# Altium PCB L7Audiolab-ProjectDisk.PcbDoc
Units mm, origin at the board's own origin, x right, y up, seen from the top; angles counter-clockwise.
Board outline 76 x 50 mm, 2 copper layers (Top Layer, Bottom Layer); 50 components, 28 nets, 135 pads, 196 vias.
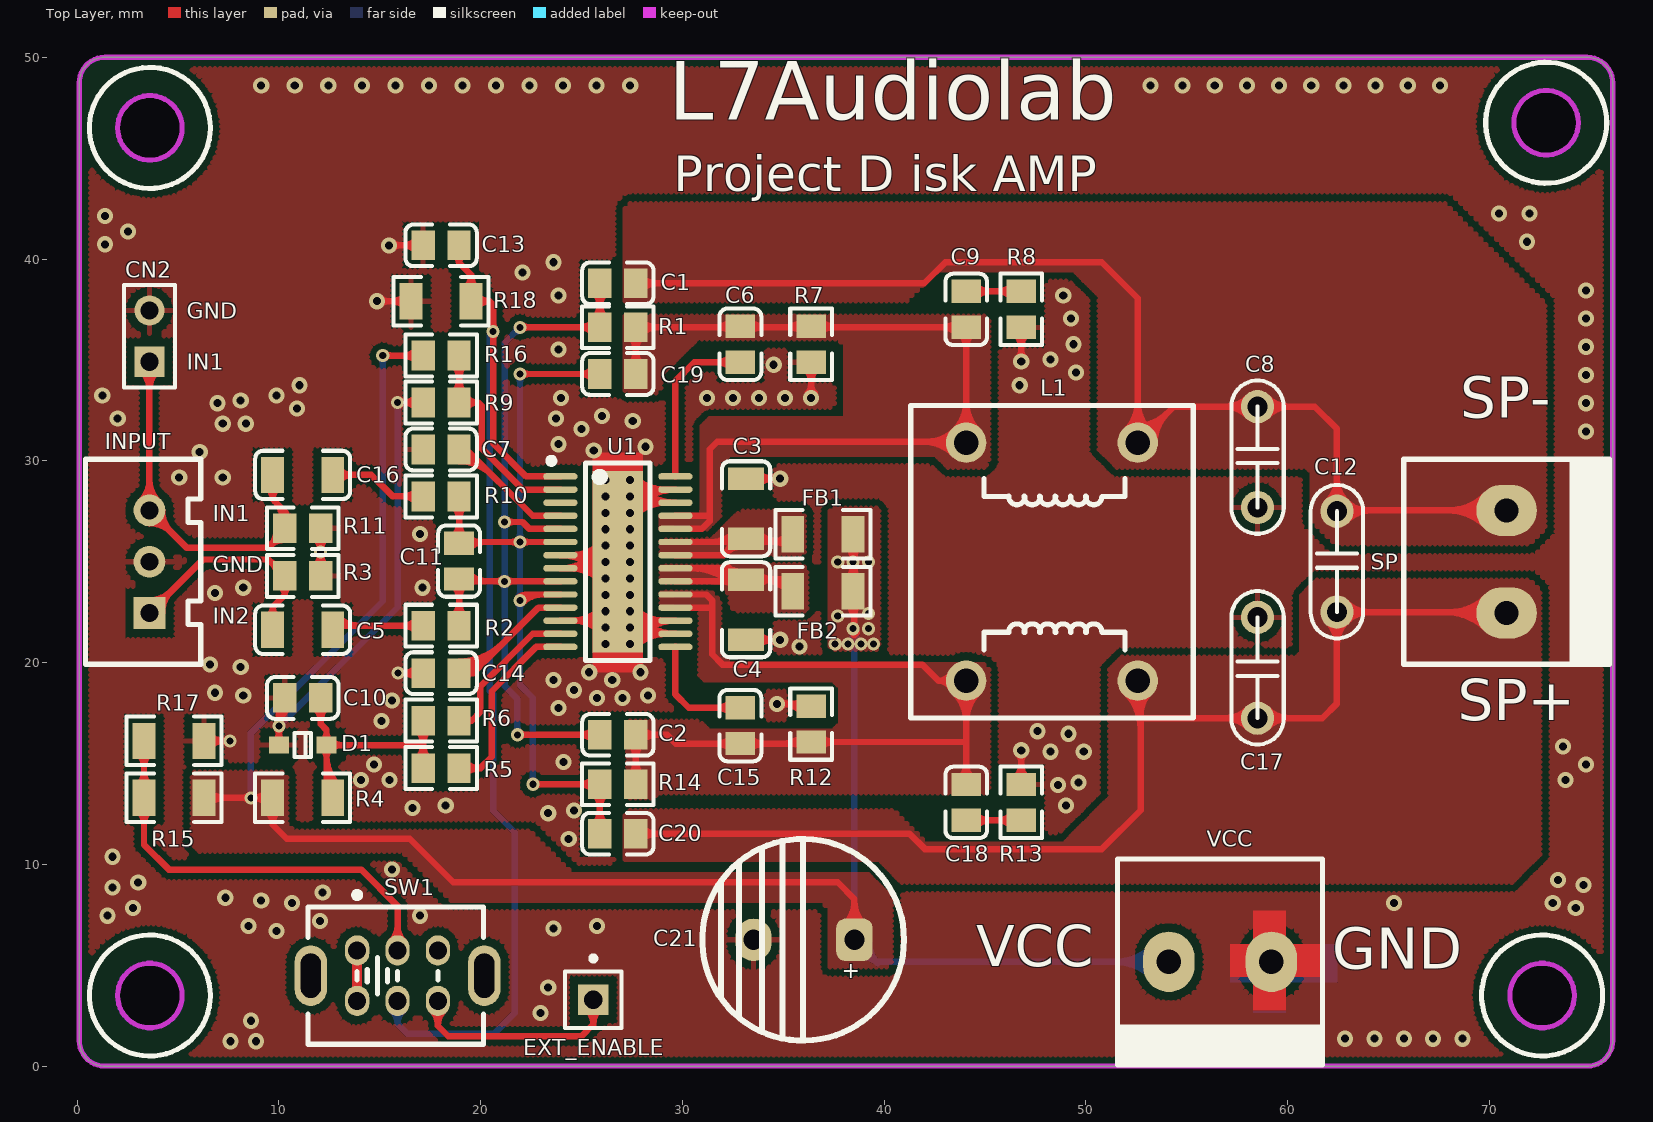
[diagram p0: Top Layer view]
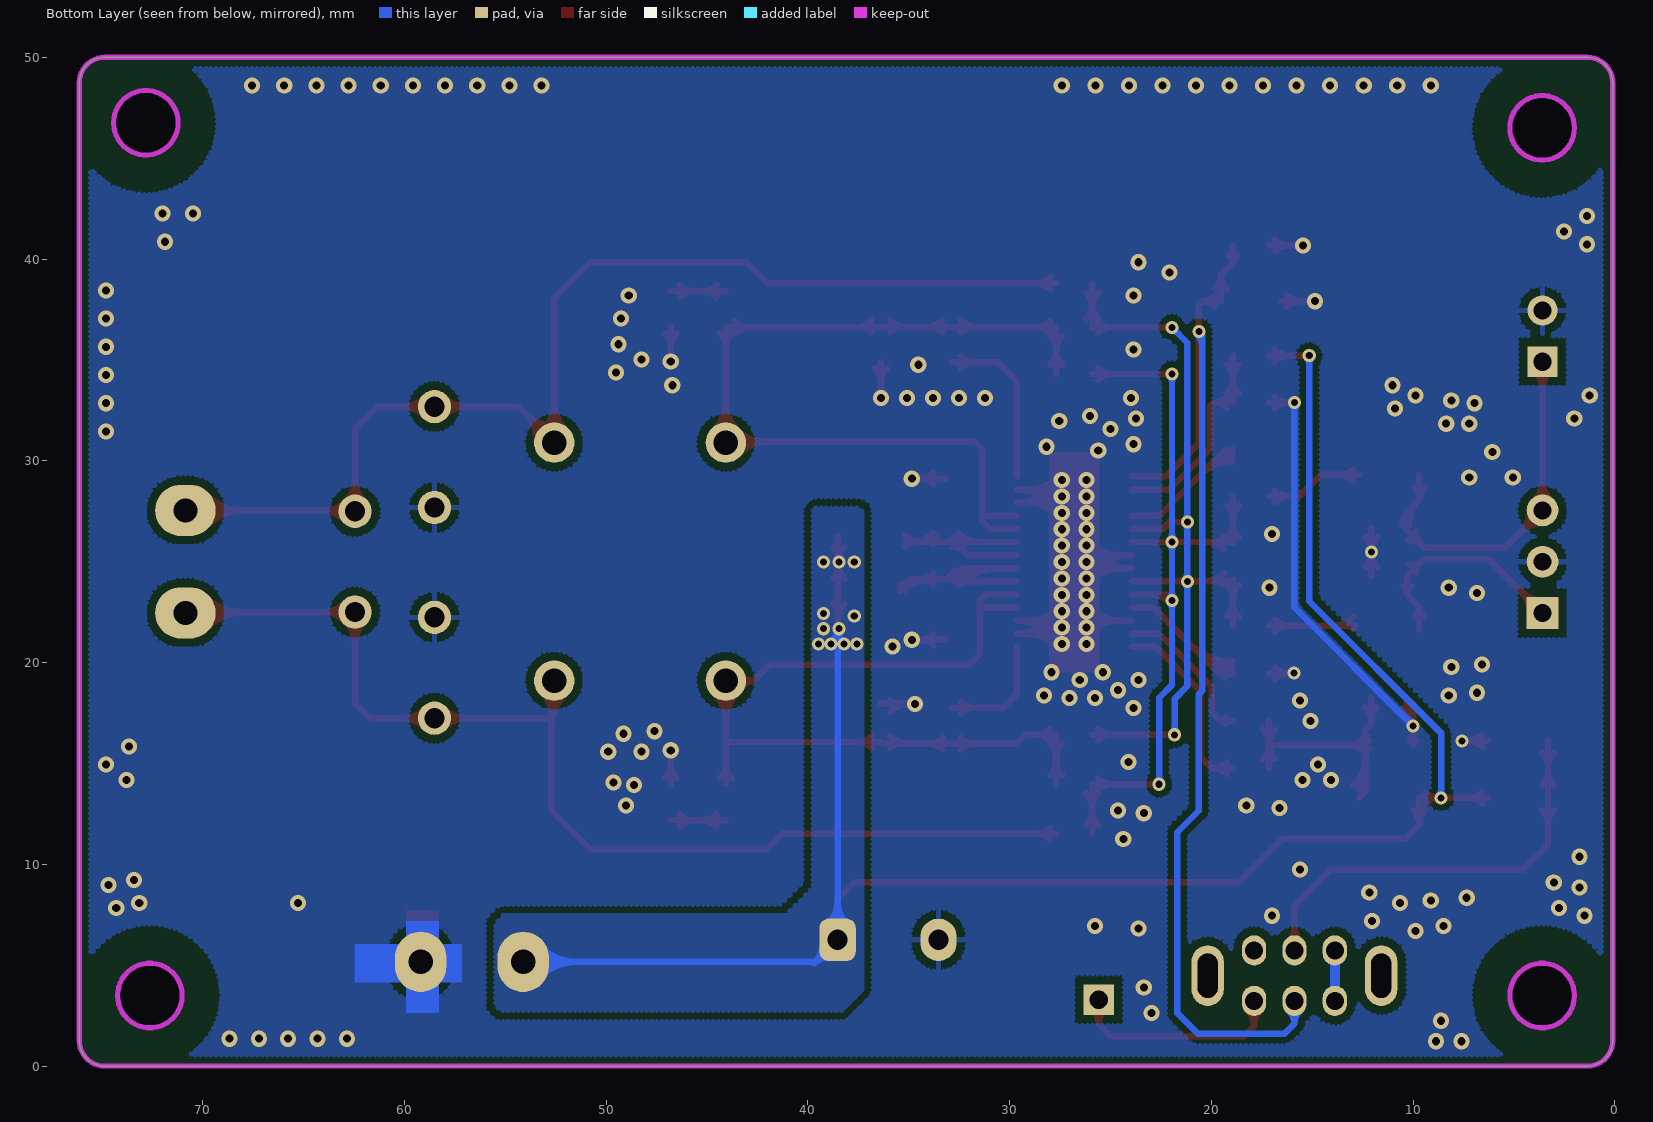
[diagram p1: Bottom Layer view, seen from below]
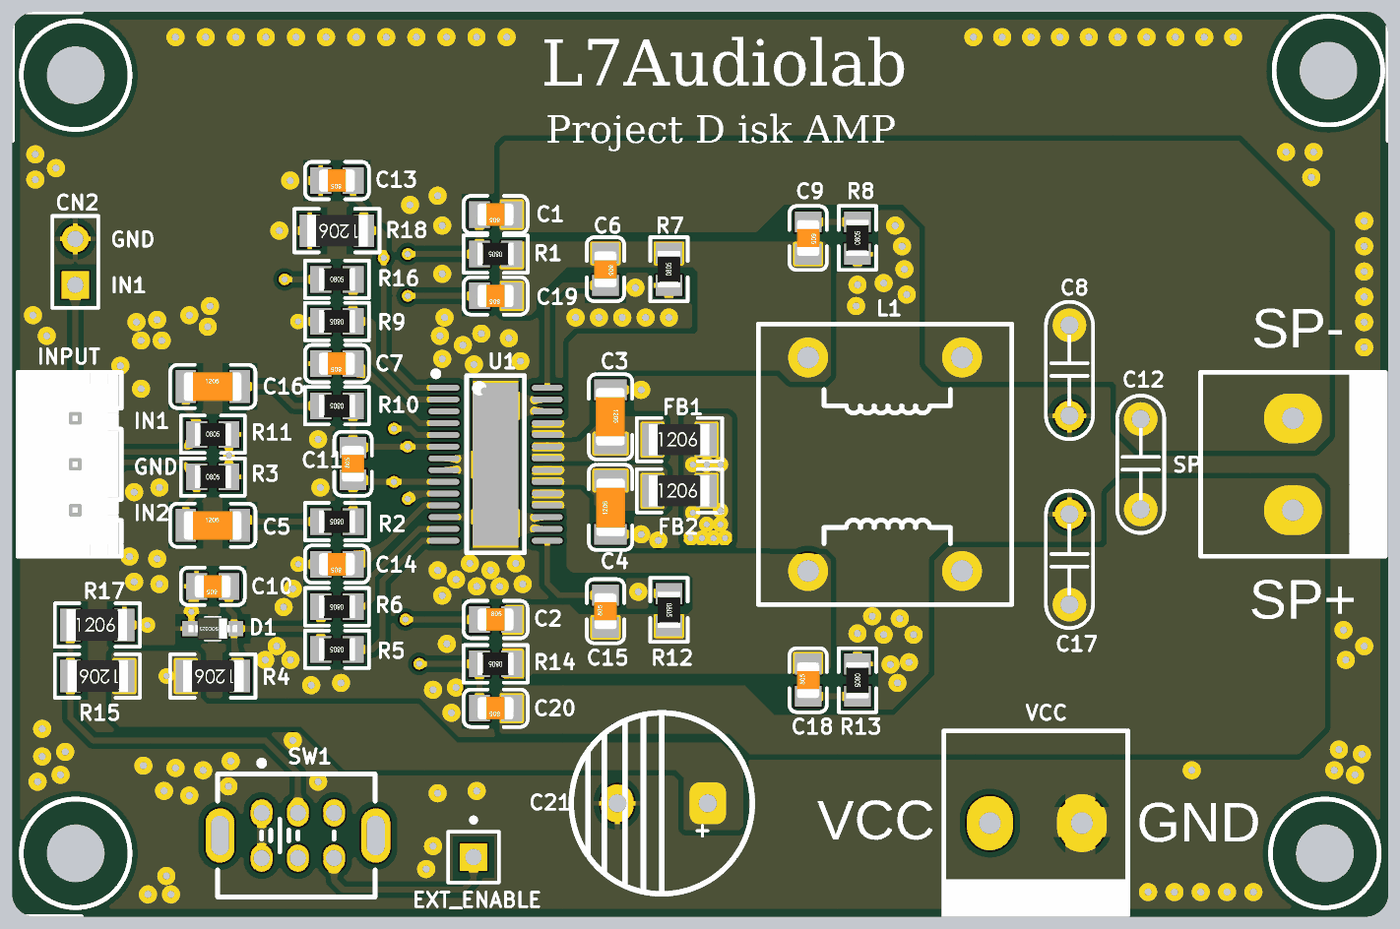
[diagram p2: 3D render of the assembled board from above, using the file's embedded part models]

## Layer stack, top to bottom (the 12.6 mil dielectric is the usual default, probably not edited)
Top Layer: signal copper 0.0356
Dielectric: dielectric 0.32, FR-4, Dk 4.8
Bottom Layer: signal copper 0.0356

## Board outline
76.106,47.714 76.106,4.153 76.106,1.27 cw(c74.836,1.27) 74.836,0 1.376,0 cw(c1.376,1.27) 0.106,1.27 0.106,48.73 cw(c1.376,48.73) 1.376,50 74.836,50 cw(c74.836,48.73) 76.106,48.73 76.106,47.841
cut-out: 72.806,48.354 ccw(c72.806,46.754) 71.206,46.754 ccw(c72.806,46.754) 72.806,45.154 ccw(c72.806,46.754) 74.406,46.754 ccw(c72.806,46.754)
cut-out: 3.606,5.1 ccw(c3.606,3.5) 2.006,3.5 ccw(c3.606,3.5) 3.606,1.9 ccw(c3.606,3.5) 5.206,3.5 ccw(c3.606,3.5)
cut-out: 3.606,48.1 ccw(c3.606,46.5) 2.006,46.5 ccw(c3.606,46.5) 3.606,44.9 ccw(c3.606,46.5) 5.206,46.5 ccw(c3.606,46.5)
cut-out: 72.606,5.1 ccw(c72.606,3.5) 71.006,3.5 ccw(c72.606,3.5) 72.606,1.9 ccw(c72.606,3.5) 74.206,3.5 ccw(c72.606,3.5)

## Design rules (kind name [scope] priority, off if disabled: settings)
Clearance Clearance_1 [IsPad] p1: gap=0.2
Clearance [All] p2: gap=0.2
HoleToHoleClearance [All] p1: gap=0 allowstackedmicrovias=TRUE
MinimumSolderMaskSliver [All] p1: minsoldermaskwidth=0
PolygonConnect PolygonConnect_1 [IsVia] p1: connectstyle=Direct reliefconductorwidth=0.254 reliefentries=4 polygonreliefangle="90 Angle"
PolygonConnect [All] p2: connectstyle=Relief reliefconductorwidth=0.254 reliefentries=4 polygonreliefangle="90 Angle"
RoutingVias [All] p1: holewidth=0.711 width=1.27 viastyle="Through Hole" minholewidth=0.711 minwidth=1.27 maxholewidth=0.711 maxwidth=1.27
SilkToSilkClearance [All] p1: silktosilkclearance=0
SilkscreenOverComponentPads [All] p1: minsilkscreentomaskgap=0
SolderMaskExpansion [All] p1: expansion=0.102
Width [All] p1: maxlimit=10 minlimit=0.1 preferedwidth=0.32
24 further rules are at their usual default settings.

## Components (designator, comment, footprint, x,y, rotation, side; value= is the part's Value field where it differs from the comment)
C1 "22pF" 0805_C 26.801,38.799 r180 top
C2 "2pF" 0805_C 26.801,16.421 r0 top
C3 "2.2uF/50V" 1206-C 33.151,27.623 r270 top
C4 "2.2uF/50V" 1206-C 33.151,22.619 r90 top
C5 "2.2uF/50V" 1206_C 11.18,21.628 r0 top
C6 "1uF/10V" 0805_C 32.872,35.776 r270 top
C7 "1uF/10V" 0805_C 18.038,30.561 r180 top
C8 "0.22uF" 独石电容5.08MM 58.501,30.182 r90 top
C9 "390pF/50V" 0805_C 44.065,37.503 r270 top
C10 "0.1uF/50V" 0805_C 11.18,18.25 r180 top
C11 "2.2nF/50V" 0805_C 18.928,25.032 r90 top
C12 "0.47uF" 独石电容5.08MM 62.438,25 r90 top
C13 "0.1uF/50V" 0805_C 18.038,40.678 r180 top
C14 "1uF/10V" 0805_C 18.038,19.478 r180 top
C15 "1uF/10V" 0805_C 32.872,16.878 r90 top
C16 "2.2uF/50V" 1206_C 11.18,29.299 r0 top
C17 "0.22uF" 独石电容5.08MM 58.501,19.742 r270 top
C18 "390pF/50V" 0805_C 44.065,13.068 r90 top
C19 "2pF" 0805_C 26.801,34.303 r180 top
C20 "22pF" 0805_C 26.801,11.519 r180 top
C21 "470uF/50V" 10*17 36.022,6.261 r180 top
CN2 "跳线帽" HDR1X2 3.586,34.912 r90 top
D1 "BZT52C4V7S" LC-SOD-323 11.18,15.913 r180 top
EXT_ENABLE "NC" PIN1 25.582,3.289 r0 top
FB1 "" 1206-R 36.961,26.361 r0 top
FB2 "" 1206-R 36.961,23.533 r0 top
INPUT "XH2.54-3PIN直" XH2.54-3PINֱ 3.586,25 r90 top
L1 "10uH" 7W14A-100M功放电感 48.315,25 r270 top
R1 "150K" 0805_R 26.801,36.614 r180 top
R2 "10K" 0805_R 18.038,21.831 r180 top
R3 "10K" 0805_R 11.18,24.295 r0 top
R4 "5.1K/1206" 1206-R 11.18,13.297 r180 top
R5 "100K" 0805_R 18.038,14.77 r180 top
R6 "100K" 0805_R 18.038,17.124 r180 top
R7 "220K" 0805_R 36.377,35.776 r90 top
R8 "10Ω" 0805_R 46.791,37.503 r90 top
R9 "5.1K" 0805_R 18.038,32.889 r180 top
R10 "10K" 0805_R 18.038,28.232 r180 top
R11 "10K" 0805_R 11.18,26.657 r0 top
R12 "220K" 0805_R 36.377,16.955 r270 top
R13 "10Ω" 0805_R 46.791,13.068 r270 top
R14 "150K" 0805_R 26.801,13.97 r180 top
R15 "100K" 1206-R 4.805,13.297 r180 top
R16 "39K" 0805_R 18.038,35.217 r0 top
R17 "13.3K" 1206-R 4.805,16.116 r0 top
R18 "200K" 1206-R 18.038,37.91 r180 top
SP "KF128 -2PIN" "KF128 -2PIN" 70.845,25 r90 top locked
SW1 "SS-22D07" SS-22D07 15.879,4.483 r0 top
U1 "MP7770" LC-TSSOP-28 26.801,25 r270 top locked
VCC "KF128 -2PIN" "KF128 -2PIN" 56.646,5.169 r0 top

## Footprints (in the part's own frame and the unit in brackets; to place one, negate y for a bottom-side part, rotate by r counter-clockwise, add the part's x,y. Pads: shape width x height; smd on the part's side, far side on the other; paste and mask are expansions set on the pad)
7W14A-100M功放电感 [mm]
  round 2 hole 1.2: 1(-5.9,-4.25) 2(-5.9,4.25) 3(5.9,-4.25) 4(5.9,4.25)
  silkscreen extent -7.75,-7 7.75,7
10*17 [mm] "插件电容50V/470UF"
  rrect50% 1.8x2.1 hole 1: 1(-2.5,0)
  oval 1.8x2.1 hole 1: 2(2.5,0)
  silkscreen extent -4.96,-5 5.04,5
0805_C [mm]
  rect 1.16x1.47 smd: 1(-0.89,0) 2(0.89,0)
  silkscreen extent -1.77,-1.04 1.77,1.04, body extent -1,-0.63 1,0.63, height 0.77
0805_R [mm]
  rect 1.16x1.47 smd: 1(-0.89,0) 2(0.89,0)
  silkscreen extent -1.77,-1.04 1.77,1.03, body extent -1,-0.63 1,0.63, height 0.49
1206-C [mm]
  rect 1.13x1.8 smd: 1(-1.49,0) 2(1.49,0)
  silkscreen extent -2.36,-1.2 2.35,1.2, body extent -1.6,-0.81 1.6,0.79, height 1
1206-R [mm] "1206贴片电阻"
  rect 1.13x1.8 smd: 1(-1.49,0) 2(1.49,0)
  silkscreen extent -2.36,-1.2 2.35,1.2, body extent -1.7,-0.86 1.65,0.87, height 0.85
1206_C [mm]
  rect 1.13x1.8 smd: 1(-1.49,0) 2(1.49,0)
  silkscreen extent -2.36,-1.2 2.35,1.2, body extent -1.6,-0.81 1.6,0.79, height 1
HDR1X2 [mm] "Connector; Header; 2 Position"
  rect 1.5x1.5 hole 0.9: 1(0,0)
  round 1.5 hole 0.9: 2(2.54,0)
  silkscreen extent -1.27,-1.27 3.81,1.27
"KF128 -2PIN" [mm] "5.08螺钉式PCB端子"
  oval 2.54x3 hole 1.2: 1(-2.54,0) 2(2.54,0)
  silkscreen extent -5.08,-5.1 5.16,5.1
LC-SOD-323 [mm]
  rect 1x0.83 smd: 1(1.18,0) 2(-1.18,0)
  silkscreen extent -0.4,-0.6 0.4,0.6, body extent -1.35,-0.63 1.35,0.63, height 1.1
LC-TSSOP-28 [mm]
  oval 0.32x1.7 smd: 1(-4.225,-2.85) 2(-3.575,-2.85) 3(-2.925,-2.85) 4(-2.275,-2.85) 5(-1.625,-2.85) 6(-0.975,-2.85) 7(-0.325,-2.85) 8(0.325,-2.85) 9(0.975,-2.85) 10(1.625,-2.85) 11(2.275,-2.85) 12(2.925,-2.85) 13(3.575,-2.85) 14(4.225,-2.85) 15(4.225,2.85) 16(3.575,2.85) 17(2.925,2.85) 18(2.275,2.85) 19(1.625,2.85) 20(0.975,2.85) 21(0.325,2.85) 22(-0.325,2.85) 23(-0.975,2.85) 24(-1.625,2.85) 25(-2.275,2.85) 26(-2.925,2.85) 27(-3.575,2.85) 28(-4.225,2.85)
  rect 9x2.5 smd: 3(0,0)
  silkscreen extent -5.15,-3.45 4.9,1.6
PIN1 [mm] "Connector; Plug"
  rect 1.5x1.5 hole 0.9: 1(0,0)
  silkscreen extent -1.4,-1.4 1.4,2.17
SS-22D07 [mm] "滑动开关"
  oval 1.6x3 hole 1 slot 2.2 at 90 deg: 0(-4.3,0) 0(4.3,0)
  oval 1.2x1.5 hole 0.9: 1(-2,1.25) 2(0,1.25) 3(2,1.25) 4(-2,-1.25) 5(0,-1.25) 6(2,-1.25)
  silkscreen extent -4.43,-3.4 4.27,4.15
XH2.54-3PINֱ [mil]
  rect 62x62 hole 34.65: 1(-100,0)
  round 62 hole 34.65: 2(0,0) 3(100,0)
  silkscreen extent -200,-100 200,125, body extent -198,-94 198,130, height 277
独石电容5.08MM [mm] "独石电容5.08MM"
  round 1.65 hole 1: 1(-2.5,0) 2(2.5,0)
  silkscreen extent -3.8,-1.3 3.8,1.3

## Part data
C1 C2 C3 C4 C5 C6 C7 C8 C9 C10 C11 C12 C13 C14 C15 C16 C17 C18 C19 C20: library part Cap, "Capacitor"
C21: library part "Cap Pol2", "Polarized Capacitor (Axial)"
CN2 SP VCC: library part "Header 2", "Header, 2-Pin"
D1: library part "Diode BAT17", "Silicon RF Schottky Diode for Mixer Applications in the VHF/UHF Range"
EXT_ENABLE: library part Socket, "Socket"
FB1 FB2: library part Inductor, "Inductor"
INPUT: library part "Header 3", "Header, 3-Pin"
L1: library part "Trans Cupl", "Transformer (Coupled Inductor Model)"
R1 R2 R3 R4 R5 R6 R7 R8 R9 R10 R11 R12 R13 R14 R15 R16 R17 R18: library part Res2, "Resistor"
SW1: library part "Header 3X2", "Header, 3-Pin, Dual row"

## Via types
v1: diameter 0.8, hole 0.4, Top Layer to Bottom Layer, 169 vias
v2: diameter 0.65, hole 0.35, Top Layer to Bottom Layer, 27 vias

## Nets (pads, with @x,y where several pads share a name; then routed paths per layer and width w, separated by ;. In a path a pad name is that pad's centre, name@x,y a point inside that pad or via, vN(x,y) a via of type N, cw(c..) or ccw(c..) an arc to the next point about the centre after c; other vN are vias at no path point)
BST1: C6.2 U1.28 | length 9.9
  Top Layer w0.32: U1.28 29.651,33.952 30.585,34.886 C6.2 ; C6.2@32.42,34.589 ccw(c31.703,33.872) 31.703,34.886 ccw(c31.703,35.9) C6.2@32.42,35.183
BST2: C15.2 U1.15 | length 7.4
  Top Layer w0.32: U1.15 29.651,18.423 30.306,17.768 C15.2 ; C15.2@32.42,17.471 ccw(c31.703,16.754) 31.703,17.768 ccw(c31.703,18.782) C15.2@32.42,18.065
EN: C13.1 R18.1 SW1.5 U1.1 | length 65.1
  Top Layer w0.32: C13.1 18.928,39.814 ; R18.1@19.244,38.533 ccw(c18.572,39.214) 19.528,39.214 ; R18.1@19.813,38.533 cw(c20.485,39.214) 19.528,39.214 ; R18.1@19.826,37.635 cw(c20.451,37.06) 20.451,37.91 ; R18.1@19.826,38.184 ccw(c20.451,38.759) 20.451,37.91 ; v2@20.502,36.294 cw(c20.221,36.013) 20.619,36.013 cw(c21.017,36.013) v2@20.736,36.294 ; v2@20.502,36.528 ccw(c20.221,36.809) 20.619,36.809 ccw(c21.017,36.809) v2@20.736,36.528 ; U1.1 22.251,29.225 20.619,30.857 v2(20.619,36.411) 20.619,37.742 20.451,37.91 ; 18.928,39.814 cw(c19.318,39.814) 19.13,40.155 ccw(c19.318,39.814) 18.928,39.814 ; 18.928,39.814 ccw(c18.539,39.814) 18.726,40.155 cw(c18.539,39.814) 18.928,39.814 ; 18.928,39.814 19.528,39.214 ; 19.528,39.214 R18.1 20.451,37.91
  Bottom Layer w0.32: SW1.5@15.585,2.756 cw(c14.991,2.096) 15.88,2.096 ; SW1.5 15.88,2.095 ; SW1.5@16.174,2.756 ccw(c16.768,2.096) 15.88,2.096 ; 20.449,35.602 cw(c21.428,35.602) v2@20.736,36.294 ; v2(20.619,36.411) 20.449,36.241 20.449,18.592 20.619,18.422 20.619,12.662 21.696,11.585 21.696,2.629 20.68,1.613 16.362,1.613 15.88,2.095
EXT_ENABLE: EXT_ENABLE.1 SW1.6 | length 16.4
  Top Layer w0.32: SW1.6@17.568,2.772 cw(c16.817,2.021) 17.88,2.021 cw(c18.942,2.021) SW1.6@18.191,2.772 ; EXT_ENABLE.1@25.271,2.828 cw(c24.52,2.077) 25.582,2.077 cw(c26.644,2.077) EXT_ENABLE.1@25.893,2.828 ; 25.582,2.057 EXT_ENABLE.1 25.582,2.07 24.998,1.486 18.394,1.486 17.88,2 ; 17.88,2 SW1.6 17.88,2
FAULT: R6.1 U1.13 | length 8.2
  Top Layer w0.32: R6.1 19.554,17.124 ; R6.1@19.317,16.965 cw(c19.554,16.868) 19.554,17.124 ; R6.1@19.317,17.283 ccw(c19.554,17.38) 19.554,17.124 ; U1.13 22.585,21.425 19.979,18.819 19.979,17.549 19.554,17.124
GND: C3.1 C4.1 C7.2 C8.1 C10.2 C13.2 C14.2 C17.1 C21.2 CN2.2 D1.1 INPUT.2 R3.2 R7.1 R8.1 R9.2 R11.2 R12.1 R13.1 R17.2 R18.2 U1.3@26.801,25 U1.7 U1.8 U1.12 U1.16 U1.17 U1.26 U1.27 VCC.2 | length 177.4
  Top Layer w0.32: R17.2 v2(7.574,16.116) ; R17.2@6.581,15.83 cw(c7.273,15.139) 7.273,16.116 cw(c7.273,17.094) R17.2@6.581,16.403 ; v2@7.457,16 ccw(c7.175,15.718) 7.175,16.116 ccw(c7.175,16.515) v2@7.457,16.233 ; D1.1@9.82,16.094 ccw(c9.385,16.529) 10,16.529 ccw(c10.616,16.529) D1.1@10.181,16.094 ; v2@9.884,16.736 cw(c9.602,16.455) 10,16.455 cw(c10.399,16.455) v2@10.117,16.736 ; v2@9.884,16.97 ccw(c9.602,17.251) 10,17.251 ccw(c10.399,17.251) v2@10.117,16.97 ; D1.1 v2(10,16.853) C10.2@10,17.96 ; v2@10,16.82 cw(c11.081,16.82) C10.2@10.512,17.738 ; 10,17.394 cw(c10.725,17.394) C10.2@10.343,18.01 ; R3.2@11.773,24.747 ccw(c11.056,25.464) 12.07,25.464 ccw(c13.084,25.464) R3.2@12.367,24.747 ; R11.2@11.773,26.205 cw(c11.056,25.488) v2(12.07,25.489) cw(c13.084,25.488) R11.2@12.367,26.205 ; v2@11.954,25.372 cw(c11.672,25.091) 12.07,25.091 cw(c12.469,25.091) v2@12.187,25.372 ; v2@11.954,25.606 ccw(c11.672,25.887) 12.07,25.887 ccw(c12.469,25.887) v2@12.187,25.606 ; R3.2 R11.2 ; v1(14.855,37.91) R18.2 ; v1@15.025,37.74 cw(c15.435,37.33) 15.435,37.91 cw(c15.435,38.489) v1@15.025,38.079 ; v1(15.455,40.678) C13.2 ; v1@15.625,40.508 cw(c16.035,40.099) 16.035,40.678 cw(c16.035,41.258) v1@15.625,40.848 ; v2(15.888,32.889) R9.2 ; v2(15.896,19.478) C14.2 ; v2@16.005,32.772 cw(c16.286,32.491) 16.286,32.889 cw(c16.286,33.287) v2@16.005,33.006 ; v2@16.013,19.361 cw(c16.295,19.079) 16.295,19.478 cw(c16.295,19.876) v2@16.013,19.594 ; R18.2@16.262,37.623 ccw(c15.571,36.932) 15.571,37.91 ccw(c15.571,38.887) R18.2@16.262,38.196 ; C14.2@16.851,19.181 ccw(c16.134,18.464) 16.134,19.478 ccw(c16.134,20.492) C14.2@16.851,19.775 ; R9.2@16.851,32.592 ccw(c16.134,31.875) 16.134,32.889 ccw(c16.134,33.903) R9.2@16.851,33.186 ; C13.2@16.851,40.381 ccw(c16.134,39.664) 16.134,40.678 ccw(c16.134,41.692) C13.2@16.851,40.975 ; U1.12 U1.3@26.476,22.075 ; U1.8@24.389,24.675 cw(c24.389,22.365) U1.3@26.022,23.998 ; U1.7@24.481,25.325 ccw(c24.481,27.505) U1.3@26.022,25.964 ; U1.12@24.483,22.075 ccw(c24.483,24.251) U1.3@26.022,22.712 ; U1.12@24.596,22.075 cw(c24.596,20.077) U1.3@26.188,21.285 ; U1.8@24.596,24.675 ccw(c24.596,26.673) U1.3@26.188,25.465 ; U1.7@24.596,25.325 cw(c24.596,23.327) U1.3@26.188,24.535 ; U1.12@24.779,22.075 cw(c24.779,20.317) U1.3@26.022,21.56 ; U1.7@24.782,25.325 cw(c24.782,23.571) U1.3@26.022,24.811 ; 24.874,24.675 ccw(c24.874,26.299) U1.3@26.022,25.151 ; 24.955,22.075 ccw(c24.955,23.597) U1.3@26.031,22.521 ; 24.955,24.675 cw(c24.955,23.153) U1.3@26.031,24.229 ; 24.955,25.325 ccw(c24.955,26.847) U1.3@26.031,25.771 ; 25.161,24.675 cw(c25.161,23.138) U1.3@26.248,24.225 ; 25.241,22.075 cw(c25.241,20.566) U1.3@26.443,21.478 ; 25.241,24.675 ccw(c25.241,26.184) U1.3@26.443,25.272 ; 25.241,25.325 cw(c25.241,23.816) U1.3@26.443,24.728 ; 25.253,25.325 ccw(c25.253,26.732) U1.3@26.248,25.737 ; 25.256,22.075 ccw(c25.256,23.478) U1.3@26.248,22.486 ; U1.3@25.552,22.075 cw(c25.552,21.09) U1.3@26.248,21.786 ; U1.3@25.554,25.325 cw(c25.554,24.344) U1.3@26.248,25.038 ; U1.3@25.646,24.675 ccw(c25.646,25.527) U1.3@26.248,24.924 ; U1.3@25.933,24.341 ccw(c23.952,22.838) U1.7 U1.3@26.476,25.325 ; U1.3@25.933,25.659 cw(c23.952,27.162) U1.8 U1.3@26.476,24.675 ; U1.3@25.934,24.675 cw(c25.934,23.91) U1.3@26.475,24.451 ; U1.3@26.026,25.325 ccw(c26.026,25.96) U1.3@26.475,25.511 ; U1.3@26.029,22.075 ccw(c26.029,22.706) U1.3@26.475,22.26 ; U1.3@27.126,21.425 U1.16 cw(c29.651,23.912) U1.3@27.67,22.409 ; U1.3@27.126,22.075 U1.17 ccw(c29.651,19.588) U1.3@27.67,21.091 ; U1.3@27.126,27.925 U1.26 cw(c29.651,30.412) U1.3@27.67,28.909 ; U1.3@27.126,28.575 U1.27 ccw(c29.651,26.088) U1.3@27.67,27.591 ; U1.3@27.128,21.2 cw(c27.672,20.656) U1.3@27.672,21.425 ; U1.3@27.128,22.26 ccw(c27.574,22.706) U1.3@27.574,22.075 ; U1.3@27.128,27.702 cw(c27.666,27.164) U1.3@27.666,27.925 ; U1.3@27.128,28.762 ccw(c27.58,29.214) U1.3@27.58,28.575 ; U1.3@27.16,21.478 cw(c28.362,20.566) 28.362,22.075 ; U1.3@27.16,22.022 ccw(c28.362,22.934) 28.362,21.425 ; U1.3@27.16,27.978 cw(c28.362,27.066) 28.362,28.575 ; U1.3@27.16,28.522 ccw(c28.362,29.434) 28.362,27.925 ; U1.3@27.354,20.974 cw(c28.444,19.884) 28.444,21.425 ; U1.3@27.354,21.673 ccw(c27.954,22.273) U1.3@27.954,21.425 ; U1.3@27.354,21.786 cw(c28.051,21.09) U1.3@28.051,22.075 ; U1.3@27.354,22.486 ccw(c28.347,23.478) 28.347,22.075 ; U1.3@27.354,27.476 cw(c28.438,26.392) 28.438,27.925 ; U1.3@27.354,28.176 ccw(c27.96,28.781) U1.3@27.96,27.925 ; U1.3@27.354,28.289 cw(c28.045,27.598) U1.3@28.045,28.575 ; U1.3@27.354,28.988 ccw(c28.353,29.987) 28.353,28.575 ; U1.3@27.415,21.285 cw(c29.007,20.077) U1.17@29.007,22.075 ; U1.3@27.415,22.215 ccw(c29.007,23.423) U1.16@29.007,21.425 ; U1.3@27.415,27.785 cw(c29.007,26.577) U1.27@29.007,28.575 ; U1.3@27.415,28.715 ccw(c29.007,29.923) U1.26@29.007,27.925 ; U1.3@27.572,20.979 cw(c28.648,19.903) 28.648,21.425 ; U1.3@27.572,22.521 ccw(c28.648,23.597) 28.648,22.075 ; U1.3@27.572,27.479 cw(c28.648,26.403) 28.648,27.925 ; U1.3@27.572,29.021 ccw(c28.648,30.097) 28.648,28.575 ; U1.3@27.581,20.747 cw(c29.217,19.111) U1.16@29.217,21.425 ; U1.3@27.581,21.56 cw(c28.824,20.317) U1.17@28.824,22.075 ; U1.3@27.581,21.9 ccw(c28.726,23.045) 28.726,21.425 ; U1.3@27.581,22.712 ccw(c29.119,24.251) U1.17@29.119,22.075 ; U1.3@27.581,27.25 cw(c29.211,25.619) U1.26@29.211,27.925 ; U1.3@27.581,28.062 cw(c28.818,26.825) U1.27@28.818,28.575 ; U1.3@27.581,28.402 ccw(c28.732,29.553) 28.732,27.925 ; U1.3@27.581,29.215 ccw(c29.125,30.759) U1.27@29.125,28.575 ; C4.1 v1(34.845,21.129) ; C3.1 v1(34.845,29.113) ; C4.1@33.773,20.842 cw(c34.464,20.151) 34.464,21.129 cw(c34.464,22.107) C4.1@33.773,21.415 ; C3.1@33.773,28.826 cw(c34.464,28.135) 34.464,29.113 cw(c34.464,30.09) C3.1@33.773,29.399 ; v1@34.675,20.959 ccw(c34.265,20.549) 34.265,21.129 ccw(c34.265,21.708) v1@34.675,21.299 ; v1@34.675,28.943 ccw(c34.265,28.533) 34.265,29.113 ccw(c34.265,29.692) v1@34.675,29.282 ; v1(34.684,17.951) R12.1@36.377,17.951 ; v1@34.854,17.782 cw(c35.263,17.372) 35.263,17.951 cw(c35.263,18.531) v1@34.854,18.121 ; v1@34.951,17.951 cw(c34.951,16.573) R12.1@35.925,17.548 ; 35.466,17.951 ccw(c35.466,18.601) R12.1@35.925,18.142 ; R7.1@36.08,34.589 cw(c35.363,33.872) 36.377,33.872 cw(c37.391,33.872) R7.1@36.674,34.589 ; v1@36.207,33.363 ccw(c35.798,33.772) 36.377,33.772 ccw(c36.957,33.772) v1@36.547,33.363 ; v1@36.377,33.193 R7.1 ; R13.1@46.494,14.255 ccw(c45.777,14.972) 46.791,14.972 ccw(c47.805,14.972) R13.1@47.088,14.255 ; R8.1@46.494,36.316 cw(c45.777,35.599) 46.791,35.599 cw(c47.805,35.599) R8.1@47.088,36.316 ; v1@46.621,15.482 cw(c46.212,15.072) 46.791,15.072 cw(c47.371,15.072) v1@46.961,15.482 ; v1@46.621,35.09 ccw(c46.212,35.499) 46.791,35.499 ccw(c47.371,35.499) v1@46.961,35.09 ; R13.1 v1(46.791,15.652) ; v1(46.791,34.92) R8.1
  Bottom Layer w0.32: v2(10,16.853) 15.888,22.74 v2(15.888,32.889) ; v2@10,17.018 ccw(c10,17.416) 10.282,17.135 ccw(c10.564,16.853) v2@10.165,16.853 ; v2@15.771,32.772 cw(c15.49,32.491) 15.888,32.491 cw(c16.286,32.491) v2@16.005,32.772
  other v1: 7.599,1.232 8.869,1.232 62.844,1.359 64.298,1.359 65.752,1.359 67.206,1.359 68.661,1.359 8.615,2.248 22.966,2.629 23.347,3.899 9.885,6.693 23.601,6.82 8.488,6.947 25.76,6.947 12.044,7.201 1.503,7.455 16.997,7.455 2.773,7.836 74.274,7.836 10.647,8.09 65.257,8.09 73.131,8.09 9.123,8.217 7.345,8.344 12.171,8.598 1.757,8.852 74.655,8.979 3.027,9.106 73.385,9.233 15.6,9.741 1.757,10.376 24.363,11.265 23.347,12.535 24.617,12.662 16.616,12.789 18.267,12.916 49.001,12.916 48.62,13.932 49.636,14.059 14.076,14.186 15.473,14.186 73.766,14.186 14.711,14.948 74.782,14.948 24.109,15.075 48.239,15.583 49.89,15.583 73.639,15.837 49.128,16.472 47.604,16.599 15.092,17.107 23.855,17.742 15.6,18.123 25.76,18.25 27.03,18.25 8.234,18.377 28.3,18.377 6.837,18.504 24.617,18.631 23.601,19.139 26.522,19.139 25.379,19.52 27.919,19.52 8.107,19.774 6.583,19.901 35.793,20.79 26.192,20.917 27.411,20.917 26.192,21.73 27.411,21.73 26.192,22.543 27.411,22.543 26.192,23.355 27.411,23.355 6.837,23.457 8.234,23.711 17.124,23.711 26.192,24.168 27.411,24.168 26.192,24.981 27.411,24.981 26.192,25.794 27.411,25.794 16.997,26.378 26.192,26.607 27.411,26.607 26.192,27.419 27.411,27.419 26.192,28.232 27.411,28.232 26.192,29.045 27.411,29.045 5.059,29.172 7.218,29.172 6.075,30.442 25.606,30.515 28.173,30.696 23.855,30.823 74.782,31.458 24.998,31.585 7.218,31.839 8.361,31.839 27.538,31.966 2.011,32.093 23.728,32.093 26.014,32.22 10.901,32.601 6.964,32.855 74.782,32.855 8.107,32.982 23.982,33.109 31.221,33.109 32.51,33.109 33.799,33.109 35.088,33.109 36.377,33.109 1.249,33.236 9.885,33.236 11.028,33.744 46.715,33.744 74.782,34.252 49.509,34.379 34.523,34.76 48.239,35.014 23.855,35.522 74.782,35.649 49.382,35.776 49.255,37.046 74.782,37.046 23.855,38.189 48.874,38.189 74.782,38.443 22.077,39.332 23.601,39.84 1.376,40.729 71.861,40.856 2.519,41.364 1.376,42.126 70.464,42.253 71.988,42.253 9.123,48.603 10.786,48.603 12.448,48.603 14.111,48.603 15.773,48.603 17.436,48.603 19.098,48.603 20.761,48.603 22.423,48.603 24.086,48.603 25.748,48.603 27.411,48.603 53.192,48.603 54.787,48.603 56.381,48.603 57.976,48.603 59.57,48.603 61.165,48.603 62.759,48.603 64.354,48.603 65.948,48.603 67.543,48.603
NetC1_1: C1.1 C8.2 C12.2 L1.2 SP.2 | length 90.6
  Top Layer w0.32: C1.1 41.991,38.799 43.032,39.84 50.779,39.84 52.565,38.054 L1.2 54.347,32.682 C8.2 61.341,32.682 62.438,31.585 C12.2 ; C1.1@27.988,38.502 cw(c28.705,37.785) 28.705,38.799 cw(c28.705,39.813) C1.1@27.988,39.096 ; L1.2@51.971,31.494 ccw(c50.537,32.928) 52.565,32.928 ccw(c54.593,32.928) L1.2@53.159,31.494 ; L1.2@52.198,31.268 ccw(c51.31,32.155) 52.565,32.155 ccw(c53.821,32.155) L1.2@52.933,31.268 ; L1.2@52.565,31.42 ccw(c52.565,32.675) 53.453,31.788 ccw(c54.341,30.9) L1.2@53.085,30.9 ; L1.2@52.565,31.74 ccw(c52.565,33.768) 53.999,32.334 ccw(c55.433,30.9) L1.2@53.405,30.9 ; C8.2@58.03,32.211 ccw(c56.895,31.076) 56.895,32.682 ccw(c56.895,34.287) C8.2@58.03,33.152 ; C8.2@58.257,32.438 ccw(c57.668,31.849) 57.668,32.682 ccw(c57.668,33.515) C8.2@58.257,32.926 ; C8.2@58.745,32.438 cw(c59.334,31.849) 59.334,32.682 cw(c59.334,33.515) C8.2@58.745,32.926 ; C8.2@58.971,32.211 cw(c60.106,31.076) 60.106,32.682 cw(c60.106,34.287) C8.2@58.971,33.152 ; C12.2@61.967,27.97 ccw(c60.832,29.105) 62.438,29.105 ccw(c64.043,29.105) 62.908,27.97 ccw(c63.946,29.009) 63.946,27.54 ; C12.2@62.194,27.744 ccw(c61.605,28.333) 62.438,28.333 ccw(c63.271,28.333) C12.2@62.682,27.744 ; C12.2@62.478,27.54 SP.2 ; C12.2@62.682,27.256 cw(c63.367,26.571) 63.367,27.54 ; C12.2@62.908,27.03 cw(c64.14,25.798) 64.14,27.54 ; SP.2@69.83,26.755 ccw(c67.935,24.86) 67.935,27.54 ccw(c67.935,30.22) SP.2@69.83,28.325 ; SP.2@70.056,26.981 ccw(c68.708,25.633) 68.708,27.54 ccw(c68.708,29.447) SP.2@70.056,28.099
NetC1_2: C1.2 C2.1 C11.1 R1.2 R2.1 U1.5 U1.9 | length 62.2
  Top Layer w0.32: R2.1@18.631,22.283 ccw(c17.914,23) 18.928,23 ccw(c19.942,23) R2.1@19.225,22.283 ; C11.1@18.631,23.845 cw(c17.914,23.128) 18.928,23.128 cw(c19.942,23.128) C11.1@19.225,23.845 ; R2.1 C11.1 ; C11.1@19.045,24.025 v2(21.188,24.025) U1.9 v2@21.509,24.025 ; C11.1@19.38,23.845 cw(c19.815,23.41) 19.815,24.025 ; C11.1@19.38,24.439 ccw(c20.379,25.438) 20.379,24.025 ; v2@21.071,23.908 ccw(c20.79,23.627) 20.79,24.025 ccw(c20.79,24.423) v2@21.071,24.142 ; v2(21.188,26.968) 22.072,26.968 22.415,26.625 U1.5 ; v2@21.305,26.851 cw(c21.586,26.569) 21.586,26.968 cw(c21.586,27.366) v2@21.305,27.085 ; v2(21.823,16.421) C2.1 ; v2@21.94,16.305 cw(c22.221,16.023) 22.221,16.421 cw(c22.221,16.82) v2@21.94,16.538 ; v2(21.95,36.614) R1.2 C1.2 ; v2@22.067,36.498 cw(c22.348,36.216) 22.348,36.614 cw(c22.348,37.013) v2@22.067,36.731 ; C2.1@25.614,16.124 ccw(c24.897,15.407) 24.897,16.421 ccw(c24.897,17.435) C2.1@25.614,16.718 ; R1.2@25.614,36.317 ccw(c24.897,35.6) 24.897,36.614 ccw(c24.897,37.628) R1.2@25.614,36.911 ; R1.2@25.614,37.066 ccw(c24.897,37.783) 25.911,37.783 ccw(c26.925,37.783) R1.2@26.208,37.066 ; C1.2@25.614,38.347 cw(c24.897,37.63) 25.911,37.63 cw(c26.925,37.63) C1.2@26.208,38.347 ; 21.586,24.025 cw(c21.586,24.423) 21.305,24.142 ccw(c21.586,24.423) 21.586,24.025 ; 21.586,24.025 ccw(c21.586,23.627) 21.305,23.908 cw(c21.586,23.627) 21.586,24.025
  Bottom Layer w0.32: v2@21.071,23.908 cw(c20.79,23.627) 21.188,23.627 cw(c21.586,23.627) v2@21.305,23.908 ; v2@21.071,24.142 ccw(c20.79,24.423) 21.188,24.423 ccw(c21.586,24.423) v2@21.305,24.142 ; v2@21.071,26.851 cw(c20.79,26.569) 21.188,26.569 cw(c21.586,26.569) v2@21.305,26.851 ; v2@21.071,27.085 ccw(c20.79,27.366) 21.188,27.366 ccw(c21.586,27.366) v2@21.305,27.085 ; v2@21.706,16.538 ccw(c21.425,16.82) 21.823,16.82 ccw(c22.221,16.82) v2@21.94,16.538 ; v2@21.785,36.614 cw(c21.387,36.614) 21.668,36.333 cw(c21.95,36.051) v2@21.95,36.449 ; v2(21.823,16.421) 21.823,18.2 21.188,18.835 v2(21.188,24.025) v2(21.188,26.968) 21.188,35.852 v2(21.95,36.614)
NetC3_2: C3.2 FB1.1 U1.22 U1.23 | length 16.1
  Top Layer w0.32: U1.22 32.039,25.325 C3.2@32.689,25.975 ; U1.23 C3.2@32.689,25.975 ; 31.458,25.975 ccw(c31.458,27.491) C3.2@32.53,26.419 ; 32.104,25.39 ccw(c31.361,26.133) C3.2@32.411,26.133 ; 32.177,25.463 cw(c32.816,24.823) C3.2@32.816,25.728 ; 32.219,25.975 cw(c32.219,25.535) C3.2@32.53,25.846 ; 32.231,25.975 ccw(c32.231,26.718) C3.2@32.756,26.193 ; C3.2@32.872,25.975 FB1.1@35.085,25.975 ; C3.2@32.872,26.158 C3.2@32.689,25.975 ; C3.2@33.547,26.193 ccw(c34.072,26.718) 34.072,25.975 ; C3.2@33.773,25.846 cw(c34.084,25.535) 34.084,25.975 ; C3.2@33.773,26.419 ccw(c34.845,27.491) 34.845,25.975 ; 34.37,25.975 ccw(c34.37,27.128) FB1.1@35.185,26.313 ; 34.617,25.975 cw(c34.617,25.172) FB1.1@35.185,25.74
NetC4_2: C4.2 FB2.1 U1.20 U1.21 | length 21
  Top Layer w0.32: U1.20 C4.2@32.763,24.025 ; U1.21 32.331,24.675 32.872,24.134 34.87,24.134 FB2.1 ; U1.21@30.472,24.675 cw(c30.472,21.764) 32.53,23.822 ccw(c32.041,23.333) 32.041,24.025 ; 31.244,24.675 cw(c31.244,22.537) C4.2@32.756,24.049 ; 31.636,24.025 ccw(c31.636,25.289) C4.2@32.53,24.395 ; 32.017,24.675 cw(c32.017,23.309) C4.2@32.983,24.275 ; C4.2@32.425,24.214 ccw(c31.923,24.348) 32.291,24.715 ccw(c32.779,25.204) C4.2@32.803,24.514 ; C4.2@33.773,23.822 cw(c34.525,23.07) 34.525,24.134 ; C4.2@33.773,24.395 ccw(c34.403,25.025) 34.403,24.134 ; C4.2@33.851,24.134 cw(c33.851,22.248) FB2.1@35.185,23.582 ; 34.624,24.134 cw(c34.624,23.021) FB2.1@35.411,23.808
NetC5_1: C5.1 INPUT.1 R3.1 | length 16.7
  Top Layer w0.32: INPUT.1 6.234,25.108 9.478,25.108 R3.1 10.29,23.354 ; INPUT.1@3.586,23.087 ccw(c3.586,24.602) 4.657,23.531 ccw(c5.728,22.46) INPUT.1@4.213,22.46 ; C5.1@9.454,22.292 ccw(c9.12,22.754) 9.69,22.754 ; 9.555,25.03 ccw(c10.023,25.498) R3.1@10.187,24.857 ; 9.683,24.903 cw(c9.231,24.45) R3.1@9.87,24.45 ; C5.1 9.69,22.754 ; C5.1@9.927,22.292 cw(c10.261,22.754) 9.69,22.754 ; R3.1@10.057,23.791 cw(c9.765,23.354) 10.29,23.354 ; R3.1@10.524,23.791 ccw(c10.815,23.354) 10.29,23.354 ; 9.69,22.754 10.29,23.354
NetC5_2: C5.2 R2.2 | length 7.4
  Top Layer w0.32: C5.2@12.874,21.831 R2.2 ; C5.2@12.957,21.677 cw(c13.33,21.304) 13.33,21.831 ; C5.2@12.957,22.25 ccw(c13.966,23.259) 13.966,21.831 ; R2.2@16.851,21.534 ccw(c16.134,20.817) 16.134,21.831 ccw(c16.134,22.845) R2.2@16.851,22.128
NetC7_1: C7.1 U1.4 | length 9.3
  Top Layer w0.32: C7.1@18.928,29.986 cw(c18.928,27.721) 20.53,29.322 ; C7.1@18.928,30.306 cw(c18.928,28.813) 19.984,29.868 ; C7.1 19.291,30.561 22.577,27.275 U1.4
NetC9_1: C9.1 R8.2 | length 5.9
  Top Layer w0.32: C9.1 R8.2 ; C9.1@44.517,38.096 cw(c45.234,37.379) 45.234,38.393 cw(c45.234,39.407) C9.1@44.517,38.69 ; R8.2@46.339,38.096 ccw(c45.622,37.379) 45.622,38.393 ccw(c45.622,39.407) R8.2@46.339,38.69
NetC10_1: C10.1 D1.2 R4.1 R5.2 R6.2 | length 22.5
  Top Layer w0.32: C10.1@11.773,17.798 cw(c11.056,17.081) 12.07,17.081 cw(c13.084,17.081) C10.1@12.367,17.798 ; C10.1 12.07,16.954 12.36,16.664 D1.2 ; D1.2@12.18,15.733 cw(c11.745,15.298) 12.36,15.298 cw(c12.976,15.298) D1.2@12.541,15.733 ; D1.2@12.18,16.094 ccw(c11.745,16.529) 12.36,16.529 ccw(c12.976,16.529) D1.2@12.541,16.094 ; 12.36,14.586 ccw(c13.624,14.586) R4.1@12.731,13.692 ; 12.36,15.358 ccw(c14.397,15.358) R4.1@12.957,13.918 ; D1.2@12.626,15.733 cw(c13.061,15.298) 13.061,15.913 cw(c13.061,16.529) D1.2@12.626,16.094 ; R4.1 12.36,13.607 D1.2 ; R5.2@16.851,15.222 ccw(c16.134,15.939) 17.148,15.939 ccw(c18.162,15.939) R5.2@17.445,15.222 ; R6.2@16.851,16.672 cw(c16.134,15.955) 17.148,15.955 cw(c18.162,15.955) R6.2@17.445,16.672 ; 17.072,15.913 D1.2 ; R5.2 R6.2
NetC11_2: C11.2 C19.2 C20.2 R10.1 R14.2 U1.6 U1.10 | length 58.8
  Top Layer w0.32: C11.2@18.631,26.219 ccw(c17.914,26.936) 18.928,26.936 ccw(c19.942,26.936) C11.2@19.225,26.219 ; R10.1@18.631,27.78 cw(c17.914,27.063) 18.928,27.063 cw(c19.942,27.063) R10.1@19.225,27.78 ; C11.2 R10.1 ; C11.2@18.982,25.975 v2(21.95,25.975) U1.6 ; C11.2@19.38,25.625 cw(c20.226,24.779) 20.226,25.975 ; C11.2@19.38,26.219 ccw(c19.969,26.807) 19.969,25.975 ; v2@21.833,25.858 ccw(c21.552,25.577) 21.552,25.975 ccw(c21.552,26.373) v2@21.833,26.092 ; v2@21.84,23.186 cw(c22.298,22.728) 22.298,23.375 ; v2(21.95,23.076) 22.249,23.375 U1.10 ; v2(21.95,34.303) C19.2 ; v2@22.067,22.959 cw(c23.07,21.956) 23.07,23.375 ; v2@22.067,25.858 cw(c22.348,25.577) 22.348,25.975 cw(c22.348,26.373) v2@22.067,26.092 ; v2@22.067,34.186 cw(c22.348,33.904) 22.348,34.303 cw(c22.348,34.701) v2@22.067,34.419 ; v2(22.585,13.97) R14.2 C20.2 ; v2@22.702,13.853 cw(c22.983,13.572) 22.983,13.97 cw(c22.983,14.368) v2@22.702,14.087 ; C20.2@25.614,11.971 ccw(c24.897,12.688) 25.911,12.688 ccw(c26.925,12.688) C20.2@26.208,11.971 ; R14.2@25.614,13.518 cw(c24.897,12.801) 25.911,12.801 cw(c26.925,12.801) R14.2@26.208,13.518 ; R14.2@25.614,13.673 ccw(c24.897,12.956) 24.897,13.97 ccw(c24.897,14.984) R14.2@25.614,14.267 ; C19.2@25.614,34.006 ccw(c24.897,33.289) 24.897,34.303 ccw(c24.897,35.317) C19.2@25.614,34.6
  Bottom Layer w0.32: v2@21.833,22.959 cw(c21.552,22.678) 21.95,22.678 cw(c22.348,22.678) v2@22.067,22.959 ; v2@21.833,23.193 ccw(c21.552,23.474) 21.95,23.474 ccw(c22.348,23.474) v2@22.067,23.193 ; v2@21.833,25.858 cw(c21.552,25.577) 21.95,25.577 cw(c22.348,25.577) v2@22.067,25.858 ; v2@21.833,26.092 ccw(c21.552,26.373) 21.95,26.373 ccw(c22.348,26.373) v2@22.067,26.092 ; v2@21.833,34.186 cw(c21.552,33.904) 21.95,33.904 cw(c22.348,33.904) v2@22.067,34.186 ; v2(21.95,34.303) v2(21.95,25.975) v2(21.95,23.076) 21.95,18.885 22.585,18.25 v2(22.585,13.97) ; v2@22.468,14.087 ccw(c22.187,14.368) 22.585,14.368 ccw(c22.983,14.368) v2@22.702,14.087
NetC12_1: C12.1 C17.2 C20.1 L1.4 SP.1 | length 84.2
  Top Layer w0.32: C20.1 41.254,11.519 42.016,10.757 50.779,10.757 52.709,12.687 52.709,18.957 L1.4 ; C20.1@27.988,11.222 cw(c28.705,10.505) 28.705,11.519 cw(c28.705,12.533) C20.1@27.988,11.816 ; L1.4@51.971,18.506 cw(c50.191,16.726) 52.709,16.726 ; L1.4@52.198,18.732 cw(c50.963,17.498) 52.709,17.498 ; 52.709,17.242 C17.2 61.709,17.242 62.438,17.971 C12.1 SP.1@70.805,22.5 ; 52.709,17.418 cw(c54.247,17.418) L1.4@53.159,18.506 ; C17.2@58.03,16.772 ccw(c56.895,15.637) 56.895,17.242 ccw(c56.895,18.848) C17.2@58.03,17.712 ; C17.2@58.257,16.998 ccw(c57.668,16.409) 57.668,17.242 ccw(c57.668,18.075) C17.2@58.257,17.486 ; C17.2@58.745,16.998 cw(c59.334,16.409) 59.334,17.242 cw(c59.334,18.075) C17.2@58.745,17.486 ; C17.2@58.971,16.772 cw(c60.106,15.637) 60.106,17.242 cw(c60.106,18.848) C17.2@58.971,17.712 ; C12.1@61.967,22.03 cw(c60.832,20.895) 62.438,20.895 cw(c64.043,20.895) 62.908,22.03 cw(c64.043,20.895) 64.043,22.5 cw(c64.043,24.105) C12.1@62.908,22.97 ; C12.1@62.194,22.256 cw(c61.605,21.667) 62.438,21.667 cw(c63.271,21.667) 62.682,22.256 cw(c63.271,21.667) 63.271,22.5 cw(c63.271,23.333) C12.1@62.682,22.744 ; 67.839,22.5 cw(c67.839,19.684) SP.1@69.83,21.675 ; 68.032,22.5 ccw(c68.032,25.043) SP.1@69.83,23.245 ; 68.611,22.5 cw(c68.611,20.456) SP.1@70.056,21.901 ; 68.804,22.5 ccw(c68.804,24.271) SP.1@70.056,23.019
NetC14_1: C14.1 U1.11 | length 12.6
  Top Layer w0.32: C14.1@18.928,19.413 ccw(c18.928,20.929) 20.001,19.857 ; C14.1 19.622,19.478 ; C14.1@18.928,19.733 ccw(c18.928,22.022) 20.547,20.403 ; C14.1@18.928,20.053 ccw(c18.928,23.115) 21.093,20.949 ; C14.1@19.301,19.283 cw(c19.622,19.116) 19.622,19.478 ; C14.1@19.301,19.672 ccw(c19.622,19.84) 19.622,19.478 ; U1.11 22.869,22.725 19.622,19.478
NetC16_1: C16.1 CN2.1 INPUT.3 R11.1 | length 30.9
  Top Layer w0.32: INPUT.3@3.142,27.984 ccw(c2.071,29.055) 3.586,29.055 ccw(c5.1,29.055) INPUT.3@4.029,27.984 ; CN2.1@3.169,34.495 cw(c2.161,33.488) 3.586,33.488 cw(c5.01,33.488) CN2.1@4.003,34.495 ; INPUT.3@3.586,26.913 cw(c3.586,25.398) 4.657,26.469 cw(c5.728,27.54) INPUT.3@4.213,27.54 ; CN2.1 INPUT.3 5.444,25.682 9.443,25.682 10.29,26.529 R11.1 10.29,27.497 ; C16.1@9.43,28.653 cw(c8.964,28.097) 9.69,28.097 ; 9.527,25.766 cw(c10.29,25.003) R11.1@10.29,26.082 ; 9.593,25.832 ccw(c8.922,26.502) R11.1@9.87,26.502 ; C16.1 9.69,28.097 ; 9.803,27.984 cw(c8.834,27.015) R11.1@10.191,26.826 ; C16.1@9.95,28.653 ccw(c10.417,28.097) 9.69,28.097 ; R11.1@10.1,27.187 ccw(c9.943,27.497) 10.29,27.497 ; 10.258,27.529 cw(c9.632,26.904) R11.1@10.508,26.782 ; R11.1@10.48,27.187 cw(c10.638,27.497) 10.29,27.497 ; 9.69,28.097 10.29,27.497
NetC16_2: C16.2 R10.2 | length 8
  Top Layer w0.32: C16.2 14.584,29.299 15.651,28.232 R10.2 ; C16.2@12.957,29.013 cw(c13.648,28.321) 13.648,29.299 cw(c13.648,30.277) C16.2@12.957,29.585 ; R10.2@16.851,27.935 ccw(c16.134,27.218) 16.134,28.232 ccw(c16.134,29.246) R10.2@16.851,28.529
NetC18_1: C18.1 R13.2 | length 5.9
  Top Layer w0.32: C18.1 R13.2 ; C18.1@44.517,11.881 cw(c45.234,11.164) 45.234,12.178 cw(c45.234,13.192) C18.1@44.517,12.475 ; R13.2@46.339,11.881 ccw(c45.622,11.164) 45.622,12.178 ccw(c45.622,13.192) R13.2@46.339,12.475
NetR15_2: R15.2 R17.1 SW1.2 | length 27.4
  Top Layer w0.32: R15.2@3.029,12.676 cw(c2.337,11.984) 3.315,11.984 cw(c4.293,11.984) R15.2@3.601,12.676 ; R15.2@3.029,13.918 ccw(c2.337,14.61) 3.315,14.61 ccw(c4.293,14.61) R15.2@3.601,13.918 ; R17.1@3.029,15.495 cw(c2.337,14.804) 3.315,14.804 cw(c4.293,14.804) R17.1@3.601,15.495 ; R17.1 R15.2 3.315,10.977 4.551,9.741 14.076,9.741 15.88,7.937 SW1.2 ; SW1.2@15.568,6.194 ccw(c14.817,6.945) 15.88,6.945 ccw(c16.942,6.945) SW1.2@16.191,6.194
NetSW1_1: SW1.1 SW1.4 | length 5
  Top Layer w0.5: SW1.4 SW1.1
  Bottom Layer w0.5: SW1.4 SW1.1
OTW: R5.1 U1.14 | length 11
  Top Layer w0.32: R5.1 19.994,14.77 20.553,15.329 20.553,18.581 22.747,20.775 U1.14 ; R5.1@19.225,14.473 cw(c19.942,13.756) 19.942,14.77 cw(c19.942,15.784) R5.1@19.225,15.067
SW1: C6.1 C9.2 C19.1 L1.1 R1.1 R7.2 U1.24 U1.25 | length 69.1
  Top Layer w0.32: C19.1@27.394,34.755 ccw(c26.677,35.472) 27.691,35.472 ccw(c28.705,35.472) C19.1@27.988,34.755 ; R1.1@27.394,36.162 cw(c26.677,35.445) 27.691,35.445 cw(c28.705,35.445) R1.1@27.988,36.162 ; C19.1 R1.1 C9.2@44.064,36.614 ; R1.1@27.988,36.317 cw(c28.705,35.6) 28.705,36.614 cw(c28.705,37.628) R1.1@27.988,36.911 ; U1.24 30.96,26.625 31.348,27.013 31.348,27.275 ; U1.25 31.348,27.275 ; 31.578,36.614 ccw(c31.578,37.805) C6.1@32.42,36.963 ; 31.828,36.614 cw(c31.828,35.777) C6.1@32.42,36.369 ; C6.1@33.324,36.369 cw(c33.916,35.777) 33.916,36.614 ; C6.1@33.324,36.963 ccw(c34.166,37.805) 34.166,36.614 ; 35.083,36.614 ccw(c35.083,37.805) R7.2@35.925,36.963 ; 35.333,36.614 cw(c35.333,35.777) R7.2@35.925,36.369 ; R7.2@36.829,36.369 cw(c37.421,35.777) 37.421,36.614 ; R7.2@36.829,36.963 ccw(c37.671,37.805) 37.671,36.614 ; 41.917,30.95 cw(c41.917,28.751) L1.1@43.471,30.306 ; 42.158,30.95 ccw(c42.158,32.807) 43.471,31.494 ccw(c42.037,32.928) 44.065,32.928 ccw(c46.093,32.928) L1.1@44.659,31.494 ; 42.689,30.95 cw(c42.689,29.524) L1.1@43.698,30.532 ; 42.894,36.614 cw(c42.894,35.597) C9.2@43.613,36.316 ; 42.899,36.614 ccw(c42.899,37.625) C9.2@43.613,36.91 ; 42.931,30.95 ccw(c42.931,32.035) 43.698,31.268 ccw(c42.81,32.155) 44.065,32.155 ccw(c45.321,32.155) L1.1@44.433,31.268 ; C9.2@43.768,36.316 cw(c43.051,35.599) 44.065,35.599 cw(c45.079,35.599) C9.2@44.362,36.316 ; C9.2 L1.1 44.015,30.95 31.729,30.95 31.348,30.569 31.348,27.275
SW2: C2.2 C15.1 C18.2 L1.3 R12.2 R14.1 U1.18 U1.19 | length 63
  Top Layer w0.32: R14.1@27.394,14.422 ccw(c26.677,15.139) 27.691,15.139 ccw(c28.705,15.139) R14.1@27.988,14.422 ; C2.2@27.394,15.969 cw(c26.677,15.252) 27.691,15.252 cw(c28.705,15.252) C2.2@27.988,15.969 ; R14.1 C2.2 29.24,16.421 29.673,15.988 C15.1 R12.2@36.301,15.988 ; C2.2@27.988,16.124 cw(c28.705,15.407) 28.705,16.421 cw(c28.705,17.435) C2.2@27.988,16.718 ; U1.18 31.475,22.725 ; U1.19 31.176,23.375 31.475,23.076 31.475,22.314 31.475,20.409 31.983,19.901 41.889,19.901 42.69,19.1 ; C15.1@32.42,15.691 ccw(c31.703,14.974) 31.703,15.988 ccw(c31.703,17.002) C15.1@32.42,16.285 ; C15.1@33.324,15.691 cw(c34.041,14.974) 34.041,15.988 cw(c34.041,17.002) C15.1@33.324,16.285 ; 35.024,15.988 ccw(c35.024,17.263) R12.2@35.925,16.362 ; 35.392,15.988 cw(c35.392,15.235) R12.2@35.925,15.768 ; R12.2 43.965,16.065 ; R12.2@36.829,15.768 cw(c37.546,15.051) 37.546,16.065 cw(c37.546,17.079) R12.2@36.829,16.362 ; L1.3@43.318,18.717 ccw(c42.69,18.394) 42.69,19.1 ; L1.3@43.318,19.483 cw(c42.69,19.806) 42.69,19.1 ; L1.3@43.471,18.506 cw(c42.037,17.072) 44.065,17.072 cw(c46.093,17.072) L1.3@44.659,18.506 ; L1.3@43.698,18.732 cw(c42.81,17.845) 44.065,17.845 cw(c45.321,17.845) L1.3@44.433,18.732 ; C18.2@43.768,14.255 ccw(c43.051,14.972) 44.065,14.972 ccw(c45.079,14.972) C18.2@44.362,14.255 ; C18.2 L1.3 42.69,19.1
UVP: R9.1 R16.2 U1.2 | length 15
  Top Layer w0.32: R9.1@18.631,33.341 ccw(c17.914,34.058) 18.928,34.058 ccw(c19.942,34.058) R9.1@19.225,33.341 ; R16.2@18.631,34.765 cw(c17.914,34.048) 18.928,34.048 cw(c19.942,34.048) R16.2@19.225,34.765 ; R16.2 R9.1 19.884,32.889 ; R9.1@19.238,32.605 cw(c19.884,32.012) 19.884,32.889 ; R9.1@19.238,33.173 ccw(c19.884,33.766) 19.884,32.889 ; U1.2 22.089,28.575 20.045,30.619 20.045,32.728 19.884,32.889
VDD: C21.1 FB1.2 FB2.2 R4.2 R15.1 R16.1 VCC.1 | length 133.9
  Top Layer w0.32: R15.1 v2(8.615,13.297) R4.2 9.69,11.968 10.393,11.265 16.489,11.265 18.648,9.106 37.698,9.106 38.522,8.282 C21.1 ; R15.1@6.581,13.011 cw(c7.273,12.319) 7.273,13.297 cw(c7.273,14.275) R15.1@6.581,13.583 ; v2@8.498,13.18 ccw(c8.217,12.899) 8.217,13.297 ccw(c8.217,13.695) v2@8.498,13.414 ; v2@8.732,13.18 cw(c9.013,12.899) 9.013,13.297 cw(c9.013,13.695) v2@8.732,13.414 ; R4.2@9.404,12.676 cw(c8.713,11.984) 9.69,11.984 cw(c10.668,11.984) R4.2@9.977,12.676 ; R4.2@9.404,13.011 ccw(c8.713,12.319) 8.713,13.297 ccw(c8.713,14.275) R4.2@9.404,13.583 ; v2(15.149,35.217) R16.1 ; v2@15.266,35.101 cw(c15.547,34.819) 15.547,35.217 cw(c15.547,35.616) v2@15.266,35.334 ; R16.1@16.851,34.92 ccw(c16.134,34.203) 16.134,35.217 ccw(c16.134,36.231) R16.1@16.851,35.514 ; C21.1@37.998,6.934 ccw(c36.735,8.198) 38.522,8.198 ccw(c40.308,8.198) C21.1@39.045,6.934 ; FB2.2@38.165,22.912 cw(c37.304,22.051) 38.522,22.051 ; FB2.2@38.165,24.155 ccw(c37.304,25.015) v2@38.522,25.015 ; FB1.2@38.165,25.74 cw(c37.304,24.879) v2@38.522,24.879 ; C21.1@38.225,6.708 ccw(c37.508,7.425) 38.522,7.425 ccw(c39.536,7.425) C21.1@38.819,6.708 ; v2@38.405,21.48 ccw(c38.123,21.762) 38.522,21.762 ccw(c38.92,21.762) v2@38.638,21.48 ; v2@38.522,21.363 FB1.2@38.522,26.291 ; 38.522,22.39 cw(c39.26,22.39) FB2.2@38.738,22.912 ; v2@38.522,24.676 ccw(c39.26,24.676) FB2.2@38.738,24.155 ; v2@38.522,25.218 cw(c39.26,25.218) FB1.2@38.738,25.74
  Bottom Layer w0.32: v2@8.498,13.414 ccw(c8.217,13.695) 8.615,13.695 ccw(c9.013,13.695) v2@8.732,13.414 ; v2(8.615,13.297) 8.615,16.513 15.149,23.047 v2(15.149,35.217) ; v2@15.032,35.101 cw(c14.751,34.819) 15.149,34.819 cw(c15.547,34.819) v2@15.266,35.101 ; C21.1@37.998,6.934 ccw(c36.735,8.198) 38.522,8.198 ccw(c40.308,8.198) C21.1@39.045,6.934 ; C21.1@38.225,6.708 ccw(c37.508,7.425) 38.522,7.425 ccw(c39.536,7.425) C21.1@38.819,6.708 ; 38.405,21.247 cw(c38.123,20.965) 38.522,20.965 cw(c38.92,20.965) 38.638,21.247 ; v2@38.522,21.363 C21.1 39.614,5.169 VCC.1 ; C21.1@38.612,5.701 cw(c38.767,4.998) C21.1@39.276,5.507 ; C21.1@38.681,5.389 cw(c38.916,4.321) 39.689,5.094 ; C21.1@39.262,6.111 ccw(c40.686,6.111) 39.679,5.104 ; VCC.1@53.322,4.384 ccw(c51.427,2.489) 51.427,5.169 ccw(c51.427,7.849) VCC.1@53.322,5.954 ; VCC.1@53.548,4.61 ccw(c52.199,3.262) 52.199,5.169 ccw(c52.199,7.076) VCC.1@53.548,5.728
  other v2: 37.571,20.917 38.206,20.917 38.841,20.917 39.476,20.917 38.46,21.679 39.222,21.679 37.698,22.314 39.222,22.441 37.698,24.981 38.46,24.981 39.222,24.981
pads on no net: SW1.0 SW1.3 U1.3@23.951,27.925

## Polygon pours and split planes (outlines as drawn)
GND on Top Layer "Bottom Layer-No Net" (hatched 90Degree grid 0.254 track 0.254, remove dead copper, pour order 1008): 5.821,50 76.433,50 76.433,36.03 76.433,0 7.599,0 0.106,0 0.106,41.999 0.106,49.746 5.567,49.746
VDD on Top Layer "Bottom Layer-No Net" (hatched 90Degree grid 0.254 track 0.254, remove dead copper, pour order 1007): 37.952,27.648 39.603,27.648 39.73,27.521 39.73,27.267 39.73,20.79 39.603,20.663 39.222,20.663 37.444,20.663 37.317,20.79 37.317,21.044 37.317,27.521 37.444,27.648 37.825,27.648
VDD on Top Layer "Bottom Layer-No Net" (hatched 90Degree grid 0.254 track 0.254, remove dead copper, pour order 1006): 6.329,14.567 10.266,14.567 10.393,14.44 10.393,14.186 10.393,12.027 10.647,11.773 10.774,11.646 11.536,11.646 22.458,11.646 23.982,10.122 24.617,9.487 28.554,9.487 39.222,9.487 39.857,8.852 40.365,8.344 40.365,7.963 40.365,5.042 40.238,4.915 39.857,4.915 37.317,4.915 37.317,5.296 37.317,7.709 37.19,7.836 36.809,8.217 32.872,8.217 18.521,8.217 16.616,10.122 16.108,10.63 11.663,10.63 6.075,10.63 5.948,10.757 5.694,11.011 5.694,11.392 5.694,14.44 5.821,14.567 6.329,14.567
NetC3_2 on Top Layer "Bottom Layer-No Net" (hatched 90Degree grid 0.254 track 0.254, remove dead copper, pour order 1005): 29.189,26.124 31.475,26.124 31.983,26.632 32.872,27.521 34.269,27.521 35.92,27.521 36.047,27.394 36.047,25.489 35.92,25.362 35.883,25.325 31.348,25.325 28.972,25.325 28.935,25.362 28.935,25.997 28.935,26.124 29.189,26.124
NetC4_2 on Top Layer "Bottom Layer-No Net" (hatched 90Degree grid 0.254 track 0.254, remove dead copper, pour order 1004): 29.316,24.854 35.92,24.854 36.047,24.727 36.174,24.6 36.174,24.473 36.174,22.695 36.047,22.568 35.92,22.568 32.618,22.568 32.364,22.822 32.364,23.33 31.983,23.711 31.729,23.965 28.935,23.965 28.935,24.854 29.316,24.854
NetC12_1 on Top Layer "Bottom Layer-No Net" (hatched 90Degree grid 0.254 track 0.254, remove dead copper, pour order 1003): 27.538,12.662 40.492,12.662 41.635,11.519 42.143,11.011 43.794,11.011 48.874,11.011 49.382,11.519 51.16,13.297 51.16,17.107 51.16,19.647 51.414,19.901 51.795,20.282 52.43,20.282 60.431,20.282 60.558,20.409 60.685,20.536 60.685,20.917 60.685,23.33 61.066,23.711 61.447,24.092 63.352,24.092 71.988,24.092 72.496,23.584 72.496,22.949 72.496,10.503 71.861,9.868 71.099,9.106 46.588,9.106 41.762,9.106 40.873,9.106 40.111,9.868 39.73,10.249 27.157,10.249 27.157,12.408 27.284,12.535 27.411,12.662 27.538,12.662
SW2 on Top Layer "Bottom Layer-No Net" (hatched 90Degree grid 0.254 track 0.254, remove dead copper, pour order 1002): 29.189,23.584 29.824,23.584 31.348,23.584 31.602,23.33 31.856,23.076 31.856,21.044 31.856,20.536 32.11,20.282 32.491,19.901 32.872,19.901 44.937,19.901 45.191,19.647 45.191,19.266 45.191,13.805 44.937,13.551 44.175,13.551 28.808,13.551 28.554,13.297 27.284,13.297 27.284,16.98 27.411,17.107 28.046,17.107 30.84,17.107 31.094,16.853 31.348,16.599 32.491,16.599 37.444,16.599 37.698,16.853 37.825,16.98 37.825,17.234 37.825,18.758 37.571,19.012 37.444,19.139 36.936,19.139 31.094,19.139 30.967,19.266 30.84,19.393 30.84,20.409 30.84,22.598 30.713,22.725 30.683,22.695 28.935,22.695 28.935,23.584 29.189,23.584
SW1 on Top Layer "Bottom Layer-No Net" (hatched 90Degree grid 0.254 track 0.254, remove dead copper, pour order 1001): 27.284,33.363 28.046,33.363 28.681,33.363 28.808,33.49 28.935,33.617 28.935,33.744 28.935,34.252 29.443,34.76 30.713,36.03 32.618,36.03 37.698,36.03 38.079,35.649 38.079,35.395 38.079,32.347 37.825,32.093 37.444,32.093 31.348,32.093 31.221,31.966 30.967,31.712 30.967,28.791 30.967,27.529 30.713,27.275 30.705,27.267 28.935,27.267 28.935,26.632 29.644,26.632 29.651,26.625 30.459,26.625 31.214,26.625 31.602,27.013 31.856,27.267 31.856,28.156 31.856,29.807 32.11,30.061 32.364,30.315 34.142,30.315 42.524,30.315 42.905,29.934 43.159,29.68 43.921,29.68 44.937,29.68 45.191,29.934 45.191,35.776 45.191,36.919 44.937,37.173 44.429,37.173 27.157,37.173 27.157,36.919 27.157,33.49 27.284,33.363
NetC1_1 on Top Layer "Bottom Layer-No Net" (hatched 90Degree grid 0.254 track 0.254, remove dead copper, pour order 1000): 27.157,37.935 29.062,37.935 41.127,37.935 42.244,39.052 42.651,39.459 44.175,39.459 49.382,39.459 49.763,39.078 50.652,38.189 50.652,33.49 50.652,30.569 51.287,29.934 51.541,29.68 52.43,29.68 60.939,29.68 61.193,29.426 61.193,28.283 61.193,27.013 61.447,26.759 62.336,25.87 70.591,25.87 71.988,25.87 72.496,26.378 72.75,26.632 72.75,26.886 72.75,37.808 70.591,39.967 67.797,42.761 50.398,42.761 30.459,42.761 27.411,42.761 27.157,42.507 27.157,42.253 27.157,37.935
GND on Bottom Layer "Bottom Layer-No Net" (hatched 90Degree grid 0.254 track 0.254, remove dead copper, pour order 1010): 5.821,50 76.433,50 76.433,36.03 76.433,0 7.599,0 0.106,0 0.106,41.999 0.106,49.746 5.567,49.746
VDD on Bottom Layer "Bottom Layer-No Net" (hatched 90Degree grid 0.254 track 0.254, remove dead copper, pour order 1009): 53.827,2.756 38.333,2.756 37.825,3.264 37.317,3.772 37.317,6.947 37.317,27.521 37.444,27.648 38.206,27.648 39.603,27.648 39.73,27.521 39.73,27.267 39.73,8.852 40.238,8.344 41.127,7.455 50.652,7.455 55.097,7.455 55.351,7.201 55.478,7.074 55.478,6.947 55.478,3.01 55.224,2.756 53.827,2.756

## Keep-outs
Keep-Out Layer:
  circle w0.254: c3.606,3.5 r1.6
  circle w0.254: c3.606,46.5 r1.6
  circle w0.254: c72.806,46.754 r1.6
  circle w0.254: c72.606,3.5 r1.6
  lines w0.254: 0.106,2.375 0.106,46.952 ; 0.106,9.106 0.106,1.27 ccw(c1.376,1.27) 1.376,0 6.456,0 ; 0.106,43.777 0.106,48.73 cw(c1.376,48.73) 1.376,50 3.916,50 ; 2.481,0 73.931,0 ; 3.154,50 74.02,50 ; 72.242,50 74.836,50 cw(c74.836,48.73) 76.106,48.73 76.106,42.888 ; 72.369,0 74.836,0 ccw(c74.836,1.27) 76.106,1.27 76.106,4.661 ; 76.106,2.175 76.106,47.914

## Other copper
Top Layer:
  rectangle net GND: 25.543,19.518 28.049,30.417
  rectangle net GND: 57.129,4.407 61.701,6.058
  rectangle net GND: 58.272,2.756 59.923,7.709
Bottom Layer:
  rectangle net GND: 58.272,2.629 59.923,7.201
  rectangle net GND: 57.129,4.153 62.463,6.058

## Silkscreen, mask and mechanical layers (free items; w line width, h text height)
Top Overlay:
  circle w0.254: c72.606,3.5 r3
  circle w0.254: c3.606,3.5 r3
  circle w0.254: c3.606,46.5 r3
  circle w0.254: c72.806,46.754 r3
  text "L7Audiolab" at 29.316,45.936 h5
  text "Project D isk AMP" at 29.57,42.761 h3
  text "GND" at 5.44,37.046 h0.8
  text "IN1" at 5.44,34.506 h0.8
  text "SP-" at 68.559,31.458 h3.5
  text "IN1" at 6.71,27.013 h0.8
  text "GND" at 6.71,24.473 h0.8
  text "IN2" at 6.71,21.933 h0.8
  text "SP+" at 68.432,16.472 h3.5
  text "VCC" at 44.556,4.28 h3.5
  text "GND" at 62.209,4.153 h3.5
Mechanical 1:
  circle w0.254: c72.606,3.5 r1.6
  circle w0.254: c72.806,46.754 r1.6
  circle w0.254: c3.606,46.5 r1.6
  circle w0.254: c3.606,3.5 r1.6
  lines w0.254: 0.106,2.375 0.106,46.952 ; 0.106,9.106 0.106,1.27 ccw(c1.376,1.27) 1.376,0 6.456,0 ; 0.106,43.777 0.106,48.73 cw(c1.376,48.73) 1.376,50 3.916,50 ; 2.481,0 73.931,0 ; 3.154,50 74.02,50 ; 72.242,50 74.836,50 cw(c74.836,48.73) 76.106,48.73 76.106,42.888 ; 72.369,0 74.836,0 ccw(c74.836,1.27) 76.106,1.27 76.106,4.661 ; 76.106,2.175 76.106,47.914

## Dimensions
3.916,50 to 1.376,0 on Top Overlay
76.106,42.888 to 0.106,48.73 on Top Overlay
